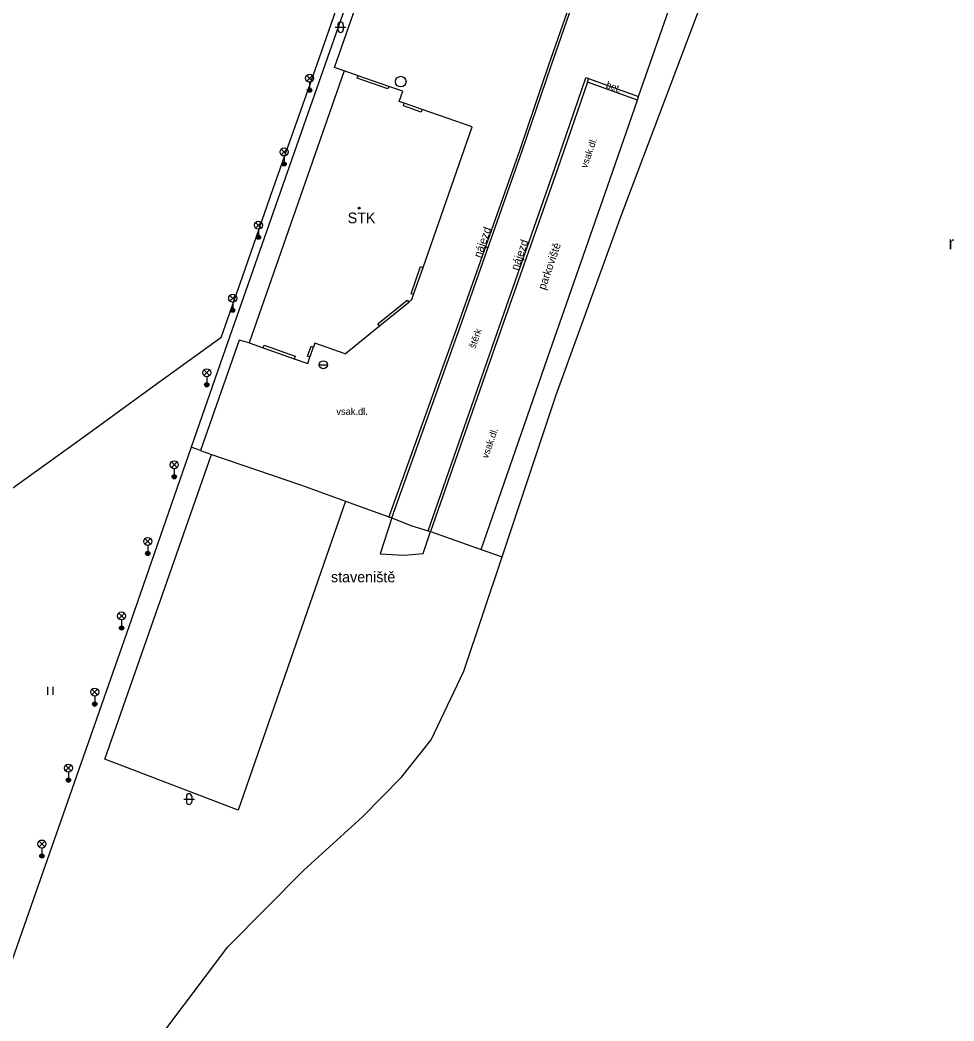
# Model space of a CAD drawing. Extents: x -596024 to -594475, y -1163820 to -1161957.
# Drawn here: x -595200.5 to -595113, y -1162203 to -1162109.2 of the extents above; entities that cross this region are included whole.
import ezdxf

# ---------------------------------------------------------------- set-up
doc = ezdxf.new("R2010")
doc.units = 0
for name, color, linetype in [('Level 10', 7, 'Continuous'), ('Level 11', 7, 'Continuous'), ('Level 27', 7, 'Continuous'), ('Level 33', 7, 'Continuous'), ('Level 35', 7, 'Continuous'), ('Level 36', 7, 'Continuous'), ('Level 39', 7, 'Continuous'), ('Level 40', 7, 'Continuous'), ('Level 41', 7, 'Continuous'), ('Level 42', 7, 'Continuous'), ('Level 5', 7, 'Continuous'), ('Level 7', 7, 'Continuous')]:
    doc.layers.add(name, color=color, linetype=linetype)

msp = doc.modelspace()

# ---------------------------------------------------------------- linework, layer by layer
at = {"layer": 'Level 10'}
msp.add_lwpolyline([(-595163.89, -1162088.15), (-595166.57, -1162095.88), (-595168.92, -1162102.61), (-595171.63, -1162101.67), (-595172.83, -1162104.66), (-595169.99, -1162105.66), (-595173.32, -1162115.23), (-595176.79, -1162125.01), (-595179.67, -1162133.29), (-595181.66, -1162138.97), (-595187.92, -1162143.5), (-595194.38, -1162148.19), (-595202.53, -1162154.04), (-595210.55, -1162159.88), (-595218.68, -1162165.75), (-595225.96, -1162171), (-595232.55, -1162175.86), (-595229.5, -1162167.18), (-595225.76, -1162156.36), (-595222.47, -1162146.91), (-595219.16, -1162137.52), (-595216.06, -1162128.59), (-595212.57, -1162118.6), (-595209.11, -1162108.7)], dxfattribs=at)
at = {"layer": 'Level 11'}
for points in [[(-595170.11, -1162113.96), (-595171.01, -1162113.64), (-595162.82, -1162090.23)], [(-595142.54, -1162116.38), (-595139.9, -1162108.78), (-595135.69, -1162096.64), (-595134.82, -1162094.15)], [(-595207.27, -1162214.29), (-595210.71, -1162220.35), (-595210.38, -1162221.03), (-595207.67, -1162222.55), (-595203.43, -1162223.32), (-595200.55, -1162222.81), (-595198.18, -1162221.37), (-595192.85, -1162213.58), (-595187.18, -1162204.27), (-595181, -1162196.05), (-595173.88, -1162188.86), (-595168.38, -1162183.86), (-595164.74, -1162180.14), (-595161.95, -1162176.66), (-595158.9, -1162170.23), (-595155.32, -1162159.5), (-595150.26, -1162144.32), (-595144.17, -1162127.56), (-595135.87, -1162105.54), (-595133.16, -1162101.48), (-595130.2, -1162099.11), (-595127.67, -1162098.14)], [(-595148.59, -1162106.61), (-595150.96, -1162113.42)], [(-595150.73, -1162113.5), (-595148.29, -1162106.45)], [(-595150.96, -1162113.42), (-595153.66, -1162121.36)], [(-595153.43, -1162121.47), (-595150.73, -1162113.5)], [(-595150.38, -1162123.08), (-595147.46, -1162114.61)], [(-595147.22, -1162114.69), (-595147.46, -1162114.61)], [(-595147.33, -1162115.01), (-595147.22, -1162114.69)], [(-595147.22, -1162114.69), (-595142.54, -1162116.38)], [(-595147.33, -1162115.01), (-595150.14, -1162123.16)], [(-595142.65, -1162116.71), (-595147.33, -1162115.01)], [(-595145.46, -1162124.8), (-595142.65, -1162116.71), (-595142.54, -1162116.38)], [(-595153.66, -1162121.36), (-595159.49, -1162137.85)], [(-595159.26, -1162137.94), (-595153.43, -1162121.47)], [(-595155.99, -1162139.13), (-595150.38, -1162123.08)], [(-595150.14, -1162123.16), (-595155.77, -1162139.23)], [(-595151.08, -1162140.9), (-595145.46, -1162124.8)], [(-595159.49, -1162137.85), (-595165.92, -1162155.75)], [(-595165.66, -1162155.84), (-595159.26, -1162137.94)], [(-595179.93, -1162139.21), (-595183.56, -1162149.54)], [(-595179.01, -1162139.45), (-595179.93, -1162139.21)], [(-595162.25, -1162157.06), (-595155.99, -1162139.13)], [(-595155.77, -1162139.23), (-595162.01, -1162157.13)], [(-595157.28, -1162158.81), (-595151.08, -1162140.9)], [(-595183.56, -1162149.54), (-595184.44, -1162149.24)], [(-595183.56, -1162149.54), (-595182.52, -1162149.9), (-595174.11, -1162152.79)], [(-595169.97, -1162154.29), (-595180.05, -1162183.23), (-595192.52, -1162178.47), (-595182.52, -1162149.9)], [(-595174.11, -1162152.79), (-595169.97, -1162154.29), (-595165.92, -1162155.75), (-595165.66, -1162155.84)], [(-595165.66, -1162155.84), (-595166.73, -1162159.22), (-595164.49, -1162159.35), (-595162.71, -1162159.18), (-595162.01, -1162157.13)], [(-595165.66, -1162155.84), (-595163.86, -1162156.57)], [(-595163.86, -1162156.57), (-595162.25, -1162157.06)], [(-595162.25, -1162157.06), (-595162.01, -1162157.13)], [(-595162.01, -1162157.13), (-595157.28, -1162158.81)], [(-595157.28, -1162158.81), (-595155.32, -1162159.5)]]:
    msp.add_lwpolyline(points, dxfattribs=at)
at = {"layer": 'Level 27'}
msp.add_circle((-595164.81, -1162114.97), 0.5, dxfattribs=at)
at = {"layer": 'Level 33'}
for p, q in [((-595173.615, -1162114.92), (-595173.085, -1162114.39)), ((-595173.615, -1162114.39), (-595173.085, -1162114.92)), ((-595173.35, -1162115.03), (-595173.35, -1162115.78)), ((-595176.005, -1162121.83), (-595175.475, -1162121.3)), ((-595176.005, -1162121.3), (-595175.475, -1162121.83)), ((-595175.74, -1162121.94), (-595175.74, -1162122.69)), ((-595178.405, -1162128.69), (-595177.875, -1162128.16)), ((-595178.405, -1162128.16), (-595177.875, -1162128.69)), ((-595178.14, -1162128.8), (-595178.14, -1162129.55)), ((-595180.815, -1162135.54), (-595180.285, -1162135.01)), ((-595180.815, -1162135.01), (-595180.285, -1162135.54)), ((-595180.55, -1162135.65), (-595180.55, -1162136.4)), ((-595183.245, -1162142.52), (-595182.715, -1162141.99)), ((-595183.245, -1162141.99), (-595182.715, -1162142.52)), ((-595182.98, -1162142.63), (-595182.98, -1162143.38)), ((-595186.285, -1162151.14), (-595185.755, -1162150.61)), ((-595186.285, -1162150.61), (-595185.755, -1162151.14)), ((-595186.02, -1162151.25), (-595186.02, -1162152)), ((-595188.775, -1162158.32), (-595188.245, -1162157.79)), ((-595188.775, -1162157.79), (-595188.245, -1162158.32)), ((-595188.51, -1162158.43), (-595188.51, -1162159.18)), ((-595191.225, -1162165.31), (-595190.695, -1162164.78)), ((-595191.225, -1162164.78), (-595190.695, -1162165.31)), ((-595190.96, -1162165.42), (-595190.96, -1162166.17)), ((-595193.735, -1162172.44), (-595193.205, -1162171.91)), ((-595193.735, -1162171.91), (-595193.205, -1162172.44)), ((-595193.47, -1162172.55), (-595193.47, -1162173.3)), ((-595196.205, -1162179.57), (-595195.675, -1162179.04)), ((-595196.205, -1162179.04), (-595195.675, -1162179.57)), ((-595195.94, -1162179.68), (-595195.94, -1162180.43)), ((-595198.685, -1162186.68), (-595198.155, -1162186.15)), ((-595198.685, -1162186.15), (-595198.155, -1162186.68)), ((-595198.42, -1162186.79), (-595198.42, -1162187.54))]:
    msp.add_line(p, q, dxfattribs=at)
for centre, radius in [((-595173.35, -1162114.655), 0.375), ((-595173.35, -1162115.78), 0.2), ((-595173.35, -1162115.78), 0.145), ((-595173.35, -1162115.78), 0.0876), ((-595175.74, -1162121.565), 0.375), ((-595175.74, -1162122.69), 0.2), ((-595175.74, -1162122.69), 0.145), ((-595175.74, -1162122.69), 0.0876), ((-595178.14, -1162128.425), 0.375), ((-595178.14, -1162129.55), 0.2), ((-595178.14, -1162129.55), 0.145), ((-595178.14, -1162129.55), 0.0876), ((-595180.55, -1162135.275), 0.375), ((-595180.55, -1162136.4), 0.2), ((-595180.55, -1162136.4), 0.145), ((-595180.55, -1162136.4), 0.0876), ((-595182.98, -1162142.255), 0.375), ((-595182.98, -1162143.38), 0.2), ((-595182.98, -1162143.38), 0.145), ((-595182.98, -1162143.38), 0.0876), ((-595186.02, -1162150.875), 0.375), ((-595186.02, -1162152), 0.2), ((-595186.02, -1162152), 0.145), ((-595186.02, -1162152), 0.0876), ((-595188.51, -1162158.055), 0.375), ((-595188.51, -1162159.18), 0.2), ((-595188.51, -1162159.18), 0.145), ((-595188.51, -1162159.18), 0.0876), ((-595190.96, -1162165.045), 0.375), ((-595190.96, -1162166.17), 0.2), ((-595190.96, -1162166.17), 0.145), ((-595190.96, -1162166.17), 0.0876), ((-595193.47, -1162172.175), 0.375), ((-595193.47, -1162173.3), 0.2), ((-595193.47, -1162173.3), 0.145), ((-595193.47, -1162173.3), 0.0876), ((-595195.94, -1162179.305), 0.375), ((-595195.94, -1162180.43), 0.2), ((-595195.94, -1162180.43), 0.145), ((-595195.94, -1162180.43), 0.0876), ((-595198.42, -1162186.415), 0.375), ((-595198.42, -1162187.54), 0.2), ((-595198.42, -1162187.54), 0.145), ((-595198.42, -1162187.54), 0.0876)]:
    msp.add_circle(centre, radius, dxfattribs=at)
at = {"layer": 'Level 35'}
msp.add_line((-595172.435, -1162141.5), (-595171.685, -1162141.5), dxfattribs=at)
msp.add_circle((-595172.06, -1162141.5), 0.375, dxfattribs=at)
at = {"layer": 'Level 36'}
for p, q in [((-595170.946, -1162109.866), (-595169.946, -1162109.866)), ((-595170.696, -1162109.616), (-595170.696, -1162110.116)), ((-595170.196, -1162109.616), (-595170.196, -1162110.116)), ((-595197.886, -1162171.677), (-595197.886, -1162172.427)), ((-595197.386, -1162171.677), (-595197.386, -1162172.427)), ((-595185.136, -1162182.206), (-595184.136, -1162182.206)), ((-595184.886, -1162181.956), (-595184.886, -1162182.456)), ((-595184.386, -1162181.956), (-595184.386, -1162182.456))]:
    msp.add_line(p, q, dxfattribs=at)
for centre, start, end in [((-595170.446, -1162109.616), 0, 180), ((-595170.446, -1162110.116), 180, 0), ((-595184.636, -1162181.956), 0, 180), ((-595184.636, -1162182.456), 180, 0)]:
    msp.add_arc(centre, 0.25, start, end, dxfattribs=at)
at = {"layer": 'Level 39'}
for radius in [0.09, 0.0398]:
    msp.add_circle((-595168.7, -1162126.82), radius, dxfattribs=at)
at = {"layer": 'Level 5'}
for points in [[(-595170.11, -1162113.96), (-595179.01, -1162139.45)], [(-595164.62, -1162115.88), (-595165.92, -1162115.43), (-595168.81, -1162114.42), (-595170.11, -1162113.96)], [(-595168.89, -1162114.65), (-595168.81, -1162114.42)], [(-595166.01, -1162115.66), (-595168.89, -1162114.65)], [(-595165.92, -1162115.43), (-595166.01, -1162115.66)], [(-595164.95, -1162116.84), (-595164.62, -1162115.88)], [(-595164.48, -1162117), (-595164.95, -1162116.84)], [(-595164.56, -1162117.24), (-595164.48, -1162117)], [(-595162.89, -1162117.82), (-595164.56, -1162117.24)], [(-595158.13, -1162119.22), (-595162.81, -1162117.58), (-595164.48, -1162117)], [(-595162.81, -1162117.58), (-595162.89, -1162117.82)], [(-595163.76, -1162135.4), (-595163.6, -1162134.93), (-595162.71, -1162132.39), (-595158.13, -1162119.22)], [(-595163.83, -1162134.85), (-595162.95, -1162132.31)], [(-595162.95, -1162132.31), (-595162.71, -1162132.39)], [(-595170.01, -1162140.48), (-595166.79, -1162137.86), (-595164.06, -1162135.64), (-595163.76, -1162135.4)], [(-595166.95, -1162137.67), (-595164.22, -1162135.45)], [(-595164.22, -1162135.45), (-595164.06, -1162135.64)], [(-595163.6, -1162134.93), (-595163.83, -1162134.85)], [(-595166.79, -1162137.86), (-595166.95, -1162137.67)], [(-595179.01, -1162139.45), (-595177.7, -1162139.91), (-595174.79, -1162140.94), (-595173.52, -1162141.39)], [(-595177.7, -1162139.91), (-595177.61, -1162139.67)], [(-595177.61, -1162139.67), (-595174.71, -1162140.7)], [(-595173.55, -1162140.7), (-595173.21, -1162139.76)], [(-595173.31, -1162140.79), (-595172.98, -1162139.85)], [(-595173.21, -1162139.76), (-595172.98, -1162139.85)], [(-595172.85, -1162139.48), (-595172.98, -1162139.85)], [(-595170.01, -1162140.48), (-595172.85, -1162139.48)], [(-595174.71, -1162140.7), (-595174.79, -1162140.94)], [(-595173.31, -1162140.79), (-595173.55, -1162140.7)], [(-595173.52, -1162141.39), (-595173.31, -1162140.79)]]:
    msp.add_lwpolyline(points, dxfattribs=at)
at = {"layer": 'Level 7'}
msp.add_lwpolyline([(-595162.39, -1162086.01), (-595162.73, -1162086.96), (-595163.56, -1162089.38), (-595167.6, -1162101.11), (-595173.5, -1162117.96), (-595181.47, -1162140.7), (-595184.44, -1162149.24), (-595190.29, -1162166.06), (-595199.21, -1162191.55), (-595205.7, -1162210.04), (-595207.27, -1162214.29), (-595223.42, -1162209.05), (-595240.94, -1162203.25), (-595242.65, -1162202.69)], dxfattribs=at)

# ---------------------------------------------------------------- texts
at = {"layer": 'Level 36'}
msp.add_text('r', height=1.2, dxfattribs=at).set_placement((-595113.503, -1162130.677))
at = {"layer": 'Level 40'}
for s, rotation, p in [('bet.', 340.19, (-595145.64, -1162115.53)), ('vsak.dl.', 70.51, (-595147.38, -1162123.13)), ('štěrk', 70.76, (-595157.83, -1162140.04)), ('vsak.dl.', 70.51, (-595156.66, -1162150.33))]:
    msp.add_text(s, height=0.65, rotation=rotation, dxfattribs=at).set_placement(p)
msp.add_text('vsak.dl.', height=0.65, dxfattribs=at).set_placement((-595170.84, -1162146.2))
at = {"layer": 'Level 41'}
msp.add_text('STK', height=1, dxfattribs=at).set_placement((-595169.78, -1162128.24))
at = {"layer": 'Level 42'}
for s, rotation, p in [('nájezd', 70.5, (-595157.31, -1162131.54)), ('nájezd', 70.74, (-595153.82, -1162132.72)), ('parkoviště', 71, (-595151.28, -1162134.54))]:
    msp.add_text(s, height=0.75, rotation=rotation, dxfattribs=at).set_placement(p)
msp.add_text('staveniště', height=1, dxfattribs=at).set_placement((-595171.34, -1162161.89))

doc.saveas('drawing.dxf')
